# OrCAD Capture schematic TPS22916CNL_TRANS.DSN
size A; title: TPS22916CNL 1-5.5V, 2A, 60 mOhm Ultra-Low Leakage Load Switch; rev: 1; note: Datasheet: SLVSDO5 EVM: SLVUCD6
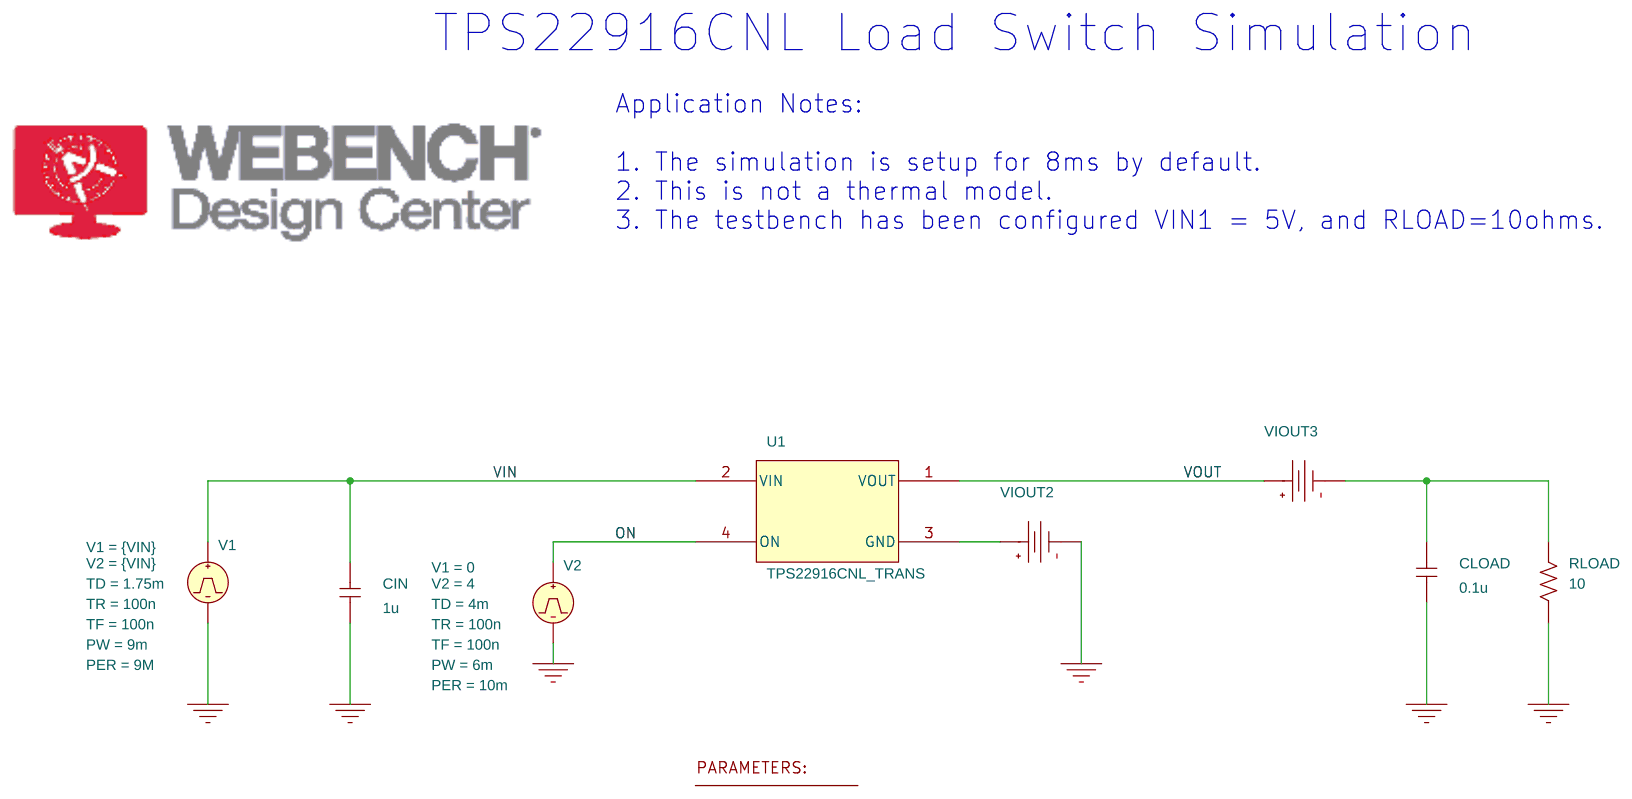
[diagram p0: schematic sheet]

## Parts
1  PARAM
CIN  1u  [RAD/CK05]
CLOAD  0.1u  [RAD/CK05]
RLOAD  10  [AX/RC05]
U1  TPS22916CNL_TRANS
V1  VPULSE
V2  VPULSE
VIOUT2  VDC
VIOUT3  VDC

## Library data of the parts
1 = PARAM: VIN: 5
CIN CLOAD = C
RLOAD = R
U1 = TPS22916CNL_TRANS
V1 = VPULSE: PER: 9M; PW: 9m; TD: 1.75m; TF: 100n; TR: 100n; V1: {VIN}; V2: {VIN}
V2 = VPULSE: PER: 10m; PW: 6m; TD: 4m; TF: 100n; TR: 100n; V1: 0; V2: 4
VIOUT2 VIOUT3 = VDC

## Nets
VIN: CIN.2 U1.2(VIN) V1.1(+)
0: CIN.1 CLOAD.1 RLOAD.1 V1.2(-) V2.2(-) VIOUT2.1(-)
ON: U1.4(ON) V2.1(+)
VOUT: U1.1(VOUT) VIOUT3.0(+)
N16770209: CLOAD.2 RLOAD.2 VIOUT3.1(-)
N16770303: U1.3(GND) VIOUT2.0(+)

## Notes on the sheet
- TPS22916CNL Load Switch Simulation
- Application Notes:
  1. The simulation is setup for 8ms by default.
  2. This is not a thermal model.
  3. The testbench has been configured VIN1 = 5V, and RLOAD=10ohms.
